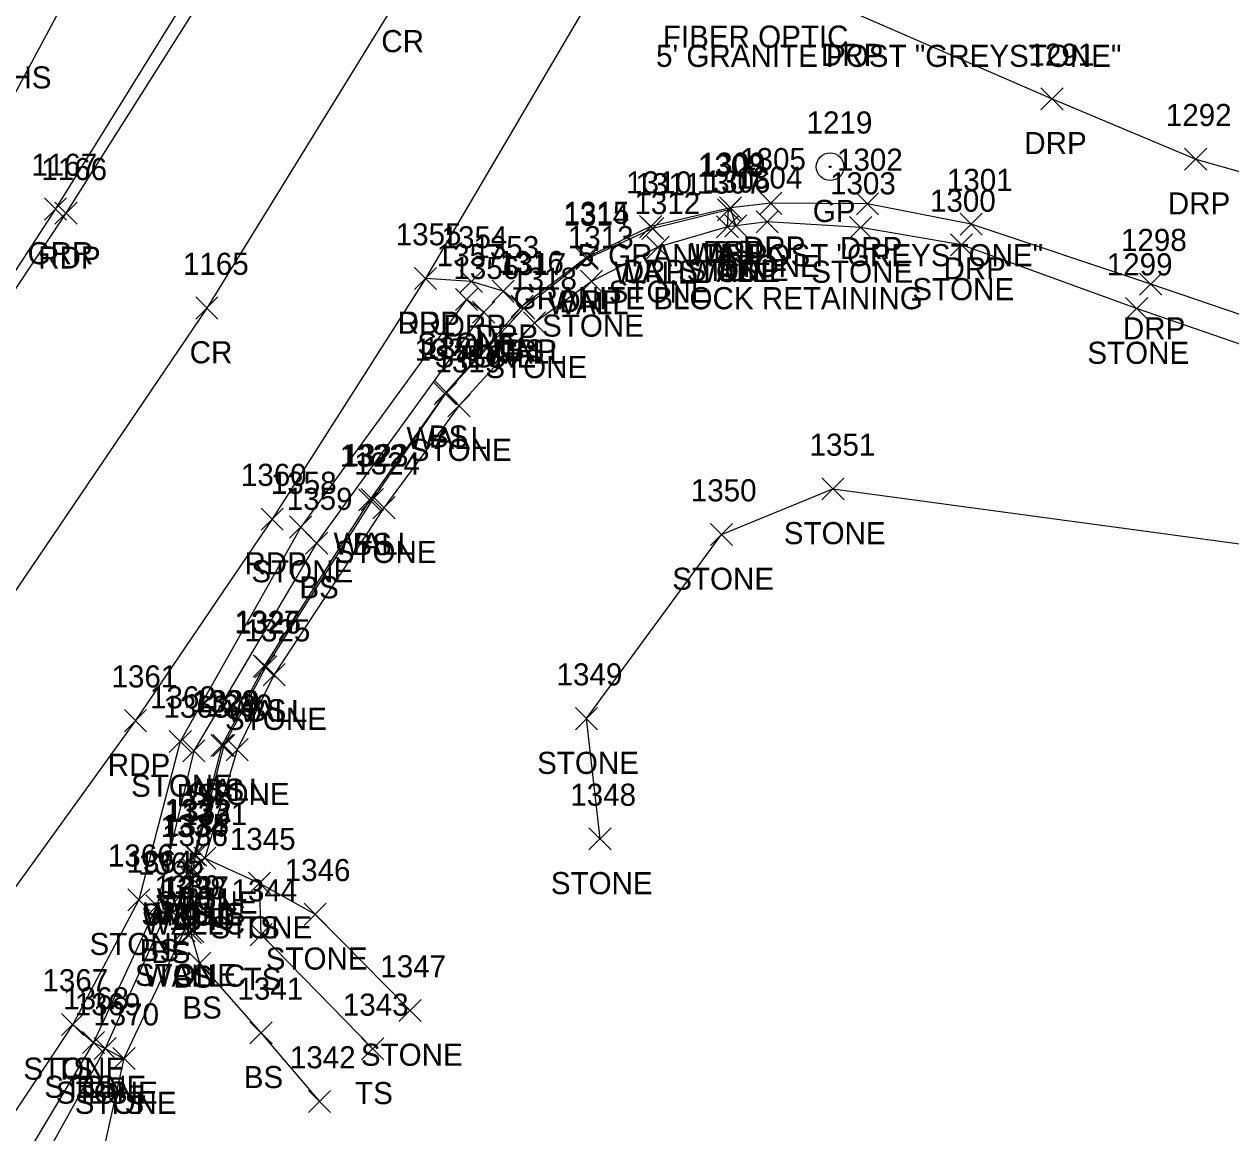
# Model space of a CAD drawing. Extents: x 1599840 to 1601211, y 518904 to 521989.
# Drawn here: x 1600815 to 1600924.1, y 521188.3 to 521288.6 of the extents above; entities that cross this region are included whole.
import ezdxf

# ---------------------------------------------------------------- set-up
doc = ezdxf.new("R2010")
doc.units = 0
for name, color, linetype in [('L_A', 7, 'Continuous'), ('L_C', 7, 'Continuous'), ('L_I', 7, 'Continuous'), ('L_TIC', 7, 'Continuous'), ('LASF', 7, 'Continuous'), ('LELB', 7, 'Continuous'), ('LW', 7, 'Continuous'), ('P_A', 7, 'Continuous'), ('P_I', 7, 'Continuous'), ('P_TIC', 7, 'Continuous'), ('PET', 7, 'Continuous'), ('PRC', 7, 'Continuous'), ('R_A', 7, 'Continuous'), ('R_C', 7, 'Continuous'), ('R_I', 7, 'Continuous'), ('R_TIC', 7, 'Continuous'), ('RDP', 7, 'Continuous'), ('RGP', 7, 'Continuous'), ('RGR', 7, 'Continuous'), ('U_A', 7, 'Continuous'), ('U_C', 7, 'Continuous')]:
    doc.layers.add(name, color=color, linetype=linetype)

msp = doc.modelspace()

# ---------------------------------------------------------------- linework, layer by layer
at = {"layer": 'L_TIC'}
for points in [[(1600877.72, 521270.83), (1600879.72, 521272.83)], [(1600879.72, 521270.83), (1600877.72, 521272.83)], [(1600877.89, 521271), (1600879.89, 521273)], [(1600879.89, 521271), (1600877.89, 521273)], [(1600881.21, 521269.74), (1600883.21, 521271.74)], [(1600883.21, 521269.74), (1600881.21, 521271.74)], [(1600870.86, 521269.14), (1600872.86, 521271.14)], [(1600872.86, 521269.14), (1600870.86, 521271.14)], [(1600877.61, 521269.29), (1600879.61, 521271.29)], [(1600879.61, 521269.29), (1600877.61, 521271.29)], [(1600877.61, 521269.29), (1600879.61, 521271.29)], [(1600879.61, 521269.29), (1600877.61, 521271.29)], [(1600878.38, 521269.38), (1600880.38, 521271.38)], [(1600880.38, 521269.38), (1600878.38, 521271.38)], [(1600878.38, 521269.38), (1600880.38, 521271.38)], [(1600880.38, 521269.38), (1600878.38, 521271.38)], [(1600889.66, 521269.22), (1600891.66, 521271.22)], [(1600891.66, 521269.22), (1600889.66, 521271.22)], [(1600871.33, 521267.43), (1600873.33, 521269.43)], [(1600873.33, 521267.43), (1600871.33, 521269.43)], [(1600898.79, 521267.65), (1600900.79, 521269.65)], [(1600900.79, 521267.65), (1600898.79, 521269.65)], [(1600864.91, 521266.38), (1600866.91, 521268.38)], [(1600866.91, 521266.38), (1600864.91, 521268.38)], [(1600865.31, 521264.35), (1600867.31, 521266.35)], [(1600867.31, 521264.35), (1600865.31, 521266.35)], [(1600854.02, 521262.72), (1600856.02, 521264.72)], [(1600856.02, 521262.72), (1600854.02, 521264.72)], [(1600859.05, 521262.1), (1600861.05, 521264.1)], [(1600861.05, 521262.1), (1600859.05, 521264.1)], [(1600855.57, 521261.56), (1600857.57, 521263.56)], [(1600857.57, 521261.56), (1600855.57, 521263.56)], [(1600855.57, 521261.56), (1600857.57, 521263.56)], [(1600857.57, 521261.56), (1600855.57, 521263.56)], [(1600859.2, 521261.92), (1600861.2, 521263.92)], [(1600861.2, 521261.92), (1600859.2, 521263.92)], [(1600914.62, 521261.89), (1600916.62, 521263.89)], [(1600916.62, 521261.89), (1600914.62, 521263.89)], [(1600860.17, 521260.6), (1600862.17, 521262.6)], [(1600862.17, 521260.6), (1600860.17, 521262.6)], [(1600852.17, 521254.32), (1600854.17, 521256.32)], [(1600854.17, 521254.32), (1600852.17, 521256.32)], [(1600852.1, 521254.18), (1600854.1, 521256.18)], [(1600854.1, 521254.18), (1600852.1, 521256.18)], [(1600853.34, 521253.11), (1600855.34, 521255.11)], [(1600855.34, 521253.11), (1600853.34, 521255.11)], [(1600887.16, 521245.58), (1600889.16, 521247.58)], [(1600889.16, 521245.58), (1600887.16, 521247.58)], [(1600845.26, 521244.59), (1600847.26, 521246.59)], [(1600847.26, 521244.59), (1600845.26, 521246.59)], [(1600845.5, 521244.63), (1600847.5, 521246.63)], [(1600847.5, 521244.63), (1600845.5, 521246.63)], [(1600846.55, 521243.88), (1600848.55, 521245.88)], [(1600848.55, 521243.88), (1600846.55, 521245.88)], [(1600839.02, 521242.13), (1600841.02, 521244.13)], [(1600841.02, 521242.13), (1600839.02, 521244.13)], [(1600877.08, 521241.45), (1600879.08, 521243.45)], [(1600879.08, 521241.45), (1600877.08, 521243.45)], [(1600840.46, 521240.68), (1600842.46, 521242.68)], [(1600842.46, 521240.68), (1600840.46, 521242.68)], [(1600835.72, 521229.56), (1600837.72, 521231.56)], [(1600837.72, 521229.56), (1600835.72, 521231.56)], [(1600835.86, 521229.49), (1600837.86, 521231.49)], [(1600837.86, 521229.49), (1600835.86, 521231.49)], [(1600836.63, 521228.78), (1600838.63, 521230.78)], [(1600838.63, 521228.78), (1600836.63, 521230.78)], [(1600864.86, 521224.8), (1600866.86, 521226.8)], [(1600866.86, 521224.8), (1600864.86, 521226.8)], [(1600828.13, 521222.73), (1600830.13, 521224.73)], [(1600830.13, 521222.73), (1600828.13, 521224.73)], [(1600829.35, 521221.88), (1600831.35, 521223.88)], [(1600831.35, 521221.88), (1600829.35, 521223.88)], [(1600831.9, 521222.37), (1600833.9, 521224.37)], [(1600833.9, 521222.37), (1600831.9, 521224.37)], [(1600832.07, 521222.37), (1600834.07, 521224.37)], [(1600834.07, 521222.37), (1600832.07, 521224.37)], [(1600833.27, 521221.99), (1600835.27, 521223.99)], [(1600835.27, 521221.99), (1600833.27, 521223.99)], [(1600866.09, 521213.92), (1600868.09, 521215.92)], [(1600868.09, 521213.92), (1600866.09, 521215.92)], [(1600829.39, 521212.52), (1600831.39, 521214.52)], [(1600831.39, 521212.52), (1600829.39, 521214.52)], [(1600829.52, 521212.46), (1600831.52, 521214.46)], [(1600831.52, 521212.46), (1600829.52, 521214.46)], [(1600830.35, 521212.17), (1600832.35, 521214.17)], [(1600832.35, 521212.17), (1600830.35, 521214.17)], [(1600829.05, 521211.08), (1600831.05, 521213.08)], [(1600831.05, 521211.08), (1600829.05, 521213.08)], [(1600829.05, 521211.08), (1600831.05, 521213.08)], [(1600831.05, 521211.08), (1600829.05, 521213.08)], [(1600829.28, 521211.17), (1600831.28, 521213.17)], [(1600831.28, 521211.17), (1600829.28, 521213.17)], [(1600829.28, 521211.17), (1600831.28, 521213.17)], [(1600831.28, 521211.17), (1600829.28, 521213.17)], [(1600829.24, 521210.27), (1600831.24, 521212.27)], [(1600831.24, 521210.27), (1600829.24, 521212.27)], [(1600835.3, 521209.92), (1600837.3, 521211.92)], [(1600837.3, 521209.92), (1600835.3, 521211.92)], [(1600835.3, 521209.92), (1600837.3, 521211.92)], [(1600837.3, 521209.92), (1600835.3, 521211.92)], [(1600824.38, 521208.42), (1600826.38, 521210.42)], [(1600826.38, 521208.42), (1600824.38, 521210.42)], [(1600826.01, 521207.86), (1600828.01, 521209.86)], [(1600828.01, 521207.86), (1600826.01, 521209.86)], [(1600827.05, 521207.69), (1600829.05, 521209.69)], [(1600829.05, 521207.69), (1600827.05, 521209.69)], [(1600840.32, 521207.1), (1600842.32, 521209.1)], [(1600842.32, 521207.1), (1600840.32, 521209.1)], [(1600828.49, 521205.62), (1600830.49, 521207.62)], [(1600830.49, 521205.62), (1600828.49, 521207.62)], [(1600829.05, 521205.46), (1600831.05, 521207.46)], [(1600831.05, 521205.46), (1600829.05, 521207.46)], [(1600829.27, 521205.55), (1600831.27, 521207.55)], [(1600831.27, 521205.55), (1600829.27, 521207.55)], [(1600835.45, 521205.26), (1600837.45, 521207.26)], [(1600837.45, 521205.26), (1600835.45, 521207.26)], [(1600829.88, 521202.67), (1600831.88, 521204.67)], [(1600831.88, 521202.67), (1600829.88, 521204.67)], [(1600848.91, 521198.4), (1600850.91, 521200.4)], [(1600850.91, 521198.4), (1600848.91, 521200.4)], [(1600818.4, 521197.14), (1600820.4, 521199.14)], [(1600820.4, 521197.14), (1600818.4, 521199.14)], [(1600818.4, 521197.14), (1600820.4, 521199.14)], [(1600820.4, 521197.14), (1600818.4, 521199.14)], [(1600820.28, 521195.5), (1600822.28, 521197.5)], [(1600822.28, 521195.5), (1600820.28, 521197.5)], [(1600820.28, 521195.5), (1600822.28, 521197.5)], [(1600822.28, 521195.5), (1600820.28, 521197.5)], [(1600835.43, 521196.38), (1600837.43, 521198.38)], [(1600837.43, 521196.38), (1600835.43, 521198.38)], [(1600821.34, 521194.97), (1600823.34, 521196.97)], [(1600823.34, 521194.97), (1600821.34, 521196.97)], [(1600821.34, 521194.97), (1600823.34, 521196.97)], [(1600823.34, 521194.97), (1600821.34, 521196.97)], [(1600845.53, 521194.93), (1600847.53, 521196.93)], [(1600847.53, 521194.93), (1600845.53, 521196.93)], [(1600823.04, 521194.05), (1600825.04, 521196.05)], [(1600825.04, 521194.05), (1600823.04, 521196.05)], [(1600823.04, 521194.05), (1600825.04, 521196.05)], [(1600825.04, 521194.05), (1600823.04, 521196.05)], [(1600823.04, 521194.05), (1600825.04, 521196.05)], [(1600825.04, 521194.05), (1600823.04, 521196.05)], [(1600840.73, 521190.17), (1600842.73, 521192.17)], [(1600842.73, 521190.17), (1600840.73, 521192.17)]]:
    msp.add_lwpolyline(points, dxfattribs=at)
at = {"layer": 'LASF'}
for points in [[(1600932.23, 521257.16), (1600915.62, 521262.89), (1600899.79, 521268.65), (1600890.66, 521270.22), (1600882.21, 521270.74), (1600879.38, 521270.38), (1600878.61, 521270.29), (1600872.33, 521268.43), (1600866.31, 521265.35), (1600861.17, 521261.6), (1600854.34, 521254.11), (1600847.55, 521244.88), (1600837.63, 521229.78), (1600834.27, 521222.99), (1600831.35, 521213.17), (1600836.3, 521210.92), (1600841.32, 521208.1), (1600849.91, 521199.4)], [(1600856.57, 521262.56), (1600855.02, 521263.72), (1600840.02, 521243.13), (1600829.13, 521223.73), (1600825.38, 521209.42), (1600819.4, 521198.14), (1600821.28, 521196.5), (1600822.34, 521195.97), (1600824.04, 521195.05)], [(1600867.09, 521214.92), (1600865.86, 521225.8), (1600878.08, 521242.45), (1600888.16, 521246.58), (1600929.62, 521240.98)], [(1600830.05, 521212.08), (1600829.49, 521206.62), (1600824.04, 521195.05)]]:
    msp.add_lwpolyline(points, dxfattribs=at)
at = {"layer": 'LELB'}
for points in [[(1600833.08, 521322.84), (1600827.14, 521306.56), (1600810.92, 521276.32), (1600800.69, 521262.52), (1600794.58, 521254.04), (1600785.73, 521239.52), (1600767.25, 521213.82), (1600747.49, 521193.49), (1600721.35, 521163.12)], [(1600879.38, 521270.38), (1600878.89, 521272)], [(1600860.05, 521263.1), (1600853.17, 521255.32), (1600846.26, 521245.59), (1600836.72, 521230.56), (1600832.9, 521223.37), (1600830.39, 521213.52), (1600830.05, 521212.08), (1600830.05, 521206.46), (1600830.88, 521203.67), (1600836.43, 521197.38), (1600841.73, 521191.17)], [(1600856.57, 521262.56), (1600841.46, 521241.68), (1600830.35, 521222.88), (1600827.01, 521208.86), (1600821.28, 521196.5), (1600810.47, 521178.41), (1600803.33, 521166.07), (1600804.2, 521165.56)], [(1600846.53, 521195.93), (1600836.45, 521206.26), (1600836.3, 521210.92)], [(1600828.05, 521208.69), (1600822.34, 521195.97), (1600812.05, 521177.48), (1600804.2, 521165.56)], [(1600819.4, 521198.14), (1600807.49, 521180.18), (1600800.87, 521166.44)], [(1600824.04, 521195.05), (1600819.31, 521173.94), (1600807, 521160.6), (1600803.28, 521163.71), (1600800.87, 521166.44)]]:
    msp.add_lwpolyline(points, dxfattribs=at)
at = {"layer": 'LW'}
for points in [[(1600878.61, 521270.29), (1600878.72, 521271.83), (1600871.86, 521270.14), (1600865.91, 521267.38), (1600860.2, 521262.92), (1600853.1, 521255.18), (1600846.5, 521245.63), (1600836.86, 521230.49), (1600833.07, 521223.37), (1600830.52, 521213.46), (1600830.28, 521212.17)], [(1600830.28, 521212.17), (1600830.24, 521211.27), (1600830.27, 521206.55)]]:
    msp.add_lwpolyline(points, dxfattribs=at)
at = {"layer": 'P_TIC'}
for points in [[(1600817.79, 521270.51), (1600819.79, 521272.51)], [(1600819.79, 521270.51), (1600817.79, 521272.51)], [(1600850.3, 521264.61), (1600852.3, 521266.61)], [(1600852.3, 521264.61), (1600850.3, 521266.61)], [(1600830.54, 521261.94), (1600832.54, 521263.94)], [(1600832.54, 521261.94), (1600830.54, 521263.94)], [(1600836.44, 521242.85), (1600838.44, 521244.85)], [(1600838.44, 521242.85), (1600836.44, 521244.85)], [(1600824.08, 521224.62), (1600826.08, 521226.62)], [(1600826.08, 521224.62), (1600824.08, 521226.62)]]:
    msp.add_lwpolyline(points, dxfattribs=at)
at = {"layer": 'PET'}
for points in [[(1600925.83, 521507.52), (1600915.18, 521473.31), (1600903.26, 521440.28), (1600887.48, 521401.44), (1600873.35, 521370.15), (1600860.38, 521343.64), (1600847.93, 521319.69), (1600844.65, 521313.14), (1600836.72, 521299.9), (1600818.79, 521271.51), (1600793.69, 521233.92), (1600774.49, 521208.06), (1600757.09, 521185.54), (1600730.91, 521154.49)], [(1600955.79, 521499.34), (1600943.51, 521460.9), (1600932.49, 521430.95), (1600915.63, 521388.21), (1600902.46, 521359.92), (1600888.21, 521330.27), (1600876.23, 521308.06), (1600874.78, 521305.59), (1600851.3, 521265.61), (1600837.44, 521243.85), (1600825.08, 521225.62), (1600799.95, 521190.82), (1600794.12, 521183.15), (1600773.8, 521157.79), (1600751.79, 521131.81)]]:
    msp.add_lwpolyline(points, dxfattribs=at)
at = {"layer": 'PRC'}
msp.add_lwpolyline([(1600941.11, 521503.3), (1600929.22, 521466.1), (1600917.95, 521435.49), (1600901.05, 521394.76), (1600888.43, 521365.83), (1600873.97, 521336.55), (1600862.78, 521315.41), (1600848.88, 521291.08), (1600831.54, 521262.94), (1600805.42, 521224.44), (1600786.95, 521198.81), (1600768.67, 521175.32), (1600742.32, 521144.02)], dxfattribs=at)
at = {"layer": 'R_TIC'}
for points in [[(1600906.97, 521280.86), (1600908.97, 521282.86)], [(1600908.97, 521280.86), (1600906.97, 521282.86)], [(1600919.96, 521275.4), (1600921.96, 521277.4)], [(1600921.96, 521275.4), (1600919.96, 521277.4)], [(1600816.84, 521270.9), (1600818.84, 521272.9)], [(1600818.84, 521270.9), (1600816.84, 521272.9)], [(1600877.89, 521271), (1600879.89, 521273)], [(1600879.89, 521271), (1600877.89, 521273)], [(1600881.54, 521271.41), (1600883.54, 521273.41)], [(1600883.54, 521271.41), (1600881.54, 521273.41)], [(1600890.29, 521271.36), (1600892.29, 521273.36)], [(1600892.29, 521271.36), (1600890.29, 521273.36)], [(1600870.67, 521269.3), (1600872.67, 521271.3)], [(1600872.67, 521269.3), (1600870.67, 521271.3)], [(1600899.66, 521269.53), (1600901.66, 521271.53)], [(1600901.66, 521269.53), (1600899.66, 521271.53)], [(1600864.92, 521266.55), (1600866.92, 521268.55)], [(1600866.92, 521266.55), (1600864.92, 521268.55)], [(1600850.3, 521264.61), (1600852.3, 521266.61)], [(1600852.3, 521264.61), (1600850.3, 521266.61)], [(1600854.45, 521264.34), (1600856.45, 521266.34)], [(1600856.45, 521264.34), (1600854.45, 521266.34)], [(1600915.89, 521264.1), (1600917.89, 521266.1)], [(1600917.89, 521264.1), (1600915.89, 521266.1)], [(1600857.33, 521263.45), (1600859.33, 521265.45)], [(1600859.33, 521263.45), (1600857.33, 521265.45)], [(1600859.05, 521262.1), (1600861.05, 521264.1)], [(1600861.05, 521262.1), (1600859.05, 521264.1)]]:
    msp.add_lwpolyline(points, dxfattribs=at)
at = {"layer": 'RDP'}
for points in [[(1600874.78, 521305.59), (1600877.36, 521296.17), (1600889.58, 521289.84), (1600907.97, 521281.86), (1600920.96, 521276.4), (1600937.85, 521271.62)], [(1600933.18, 521259.54), (1600916.89, 521265.1), (1600900.66, 521270.53), (1600891.29, 521272.36), (1600882.54, 521272.41), (1600878.89, 521272), (1600871.67, 521270.3), (1600865.92, 521267.55), (1600860.05, 521263.1), (1600858.33, 521264.45), (1600855.45, 521265.34), (1600851.3, 521265.61)]]:
    msp.add_lwpolyline(points, dxfattribs=at)
at = {"layer": 'RGP'}
msp.add_line((1600887.9, 521275.72), (1600887.9, 521275.72), dxfattribs=at)
for radius in [1.25, 0.0833]:
    msp.add_circle((1600887.9, 521275.72), radius, dxfattribs=at)
at = {"layer": 'RGR'}
msp.add_lwpolyline([(1600826.09, 521344.21), (1600833.69, 521339.74), (1600838.12, 521335.63), (1600842.43, 521329.4), (1600844.67, 521324.01), (1600845, 521318.73), (1600843.51, 521313.73), (1600835.63, 521300.64), (1600817.84, 521271.9), (1600810.24, 521260.24), (1600806.53, 521256.68), (1600802.26, 521254.42), (1600799.01, 521253.84)], dxfattribs=at)

# ---------------------------------------------------------------- texts
at = {"layer": 'L_A'}
for s, p in [('WALL', (1600875.21, 521266.83)), ('BS', (1600877.33, 521267)), ('STONE', (1600874.16, 521265.29)), ('STONE', (1600874.92, 521265.38)), ('WALL', (1600875.1, 521265.29)), ('STONE', (1600877.75, 521265.74)), ('BS', (1600877.82, 521265.38)), ('STONE', (1600886.2, 521265.22)), ('WALL', (1600868.34, 521265.14)), ('STONE', (1600867.87, 521263.43)), ('STONE', (1600895.33, 521263.65)), ('WALL', (1600862.4, 521262.38)), ('STONE', (1600861.85, 521260.35)), ('STONE', (1600850.56, 521258.72)), ('STONE', (1600852.12, 521257.56)), ('BS', (1600855.01, 521257.56)), ('WALL', (1600856.69, 521257.92)), ('BS', (1600858.49, 521258.1)), ('STONE', (1600911.16, 521257.89)), ('STONE', (1600856.72, 521256.6)), ('WALL', (1600849.59, 521250.18)), ('BS', (1600851.61, 521250.32)), ('STONE', (1600849.89, 521249.11)), ('STONE', (1600883.71, 521241.58)), ('WALL', (1600842.99, 521240.63)), ('BS', (1600844.7, 521240.59)), ('STONE', (1600843.09, 521239.88)), ('STONE', (1600835.56, 521238.13)), ('STONE', (1600873.62, 521237.45)), ('BS', (1600839.9, 521236.68)), ('WALL', (1600833.35, 521225.49)), ('BS', (1600835.16, 521225.56)), ('STONE', (1600833.17, 521224.78)), ('STONE', (1600861.4, 521220.8)), ('STONE', (1600824.68, 521218.73)), ('WALL', (1600829.55, 521218.37)), ('BS', (1600831.34, 521218.37)), ('BS', (1600828.79, 521217.88)), ('STONE', (1600829.81, 521217.99)), ('STONE', (1600862.64, 521209.92)), ('WALL', (1600827.01, 521208.46)), ('BS', (1600828.83, 521208.52)), ('STONE', (1600826.9, 521208.17)), ('STONE', (1600825.59, 521207.08)), ('WALLC', (1600825.78, 521206.27)), ('WALLC', (1600825.82, 521207.17)), ('WALL', (1600826.77, 521207.17)), ('BS', (1600828.49, 521207.08)), ('STONE', (1600831.85, 521205.92)), ('TS', (1600834.71, 521205.92)), ('STONE', (1600820.92, 521204.42)), ('BS', (1600825.45, 521203.86)), ('BS', (1600826.49, 521203.69)), ('STONE', (1600836.86, 521203.1)), ('STONE', (1600825.03, 521201.62)), ('WALLC', (1600825.81, 521201.55)), ('BS', (1600828.49, 521201.46)), ('TS', (1600834.86, 521201.26)), ('BS', (1600829.32, 521198.67)), ('STONE', (1600845.46, 521194.4)), ('STONE', (1600814.94, 521193.14)), ('TS', (1600817.81, 521193.14)), ('BS', (1600834.87, 521192.38)), ('STONE', (1600816.83, 521191.5)), ('STONE', (1600817.88, 521190.97)), ('BS', (1600819.72, 521191.5)), ('BS', (1600820.78, 521190.97)), ('STONE', (1600819.58, 521190.05)), ('STONE', (1600819.58, 521190.05)), ('TS', (1600822.45, 521190.05)), ('TS', (1600844.94, 521190.93))]:
    msp.add_text(s, height=2, dxfattribs=at).set_placement(p)
at = {"layer": 'L_C'}
msp.add_text('GRANITE BLOCK RETAINING', height=2, dxfattribs=at).set_placement((1600859.28, 521262.83))
at = {"layer": 'L_I'}
for s, p in [('1309', (1600876.11, 521275)), ('1308', (1600875.95, 521274.83)), ('1311', (1600870.3, 521273.14)), ('1307', (1600875.84, 521273.29)), ('1307', (1600875.84, 521273.29)), ('1306', (1600876.55, 521273.38)), ('1306', (1600876.55, 521273.38)), ('1304', (1600879.44, 521273.74)), ('1303', (1600887.89, 521273.22)), ('1312', (1600870.2, 521271.43)), ('1300', (1600896.93, 521271.65)), ('1314', (1600863.78, 521270.38)), ('1313', (1600864.18, 521268.35)), ('1357', (1600852.32, 521266.72)), ('1356', (1600853.83, 521265.56)), ('1356', (1600853.83, 521265.56)), ('1316', (1600857.87, 521266.1)), ('1317', (1600858.07, 521265.92)), ('1299', (1600912.92, 521265.89)), ('1318', (1600859.05, 521264.6)), ('1320', (1600850.32, 521258.18)), ('1321', (1600851.04, 521258.32)), ('1319', (1600852.21, 521257.11)), ('1351', (1600886.04, 521249.58)), ('1322', (1600843.56, 521248.59)), ('1323', (1600843.81, 521248.63)), ('1324', (1600844.86, 521247.88)), ('1358', (1600837.32, 521246.13)), ('1359', (1600838.76, 521244.68)), ('1350', (1600875.3, 521245.45)), ('1327', (1600834.03, 521233.56)), ('1326', (1600834.11, 521233.49)), ('1325', (1600834.94, 521232.78)), ('1349', (1600863.16, 521228.8)), ('1362', (1600826.39, 521226.73)), ('1363', (1600827.61, 521225.88)), ('1328', (1600830.21, 521226.37)), ('1329', (1600830.36, 521226.37)), ('1330', (1600831.49, 521225.99)), ('1348', (1600864.4, 521217.92)), ('1333', (1600827.69, 521216.52)), ('1332', (1600827.83, 521216.46)), ('1331', (1600829.23, 521216.17)), ('1334', (1600827.35, 521215.08)), ('1334', (1600827.35, 521215.08)), ('1335', (1600827.59, 521215.17)), ('1335', (1600827.59, 521215.17)), ('1336', (1600827.49, 521214.27)), ('1345', (1600833.61, 521213.92)), ('1345', (1600833.61, 521213.92)), ('1366', (1600822.58, 521212.42)), ('1364', (1600824.27, 521211.86)), ('1365', (1600825.31, 521211.69)), ('1346', (1600838.57, 521211.1)), ('1339', (1600826.79, 521209.62)), ('1337', (1600827.58, 521209.55)), ('1338', (1600827.35, 521209.46)), ('1344', (1600833.76, 521209.26)), ('1340', (1600828.1, 521206.67)), ('1347', (1600847.22, 521202.4)), ('1367', (1600816.66, 521201.14)), ('1367', (1600816.66, 521201.14)), ('1341', (1600834.3, 521200.38)), ('1368', (1600818.54, 521199.5)), ('1368', (1600818.54, 521199.5)), ('1369', (1600819.59, 521198.97)), ('1369', (1600819.59, 521198.97)), ('1343', (1600843.83, 521198.93)), ('1370', (1600821.26, 521198.05)), ('1370', (1600821.26, 521198.05)), ('1370', (1600821.26, 521198.05)), ('1342', (1600839.04, 521194.17))]:
    msp.add_text(s, height=2, dxfattribs=at).set_placement(p)
at = {"layer": 'P_A'}
for s, p in [('CR', (1600847.31, 521286.08)), ('RDP', (1600816.28, 521266.51)), ('RDP', (1600848.79, 521260.61)), ('CR', (1600829.98, 521257.94)), ('RDP', (1600834.93, 521238.85)), ('RDP', (1600822.57, 521220.62))]:
    msp.add_text(s, height=2, dxfattribs=at).set_placement(p)
at = {"layer": 'P_I'}
for s, p in [('1166', (1600816.56, 521274.51)), ('1355', (1600848.61, 521268.61)), ('1165', (1600829.37, 521265.94)), ('1360', (1600834.61, 521246.85)), ('1361', (1600822.91, 521228.62))]:
    msp.add_text(s, height=2, dxfattribs=at).set_placement(p)
at = {"layer": 'R_A'}
for s, p in [('DRP', (1600887.07, 521284.84)), ('DRP', (1600905.46, 521276.86)), ('GP', (1600886.33, 521270.72)), ('DRP', (1600918.44, 521271.4)), ('DRP', (1600880.02, 521267.41)), ('GRR', (1600815.32, 521266.9)), ('DRP', (1600876.38, 521267)), ('DRP', (1600888.78, 521267.36)), ('DRP', (1600869.15, 521265.3)), ('DRP', (1600898.15, 521265.53)), ('DRP', (1600863.41, 521262.55)), ('DRP', (1600848.79, 521260.61)), ('DRP', (1600852.94, 521260.34)), ('DRP', (1600914.38, 521260.1)), ('DRP', (1600855.82, 521259.45)), ('DRP', (1600857.54, 521258.1))]:
    msp.add_text(s, height=2, dxfattribs=at).set_placement(p)
at = {"layer": 'R_C'}
for p in [(1600872.16, 521284.75), (1600865.08, 521266.72)]:
    msp.add_text('5\' GRANITE POST "GREYSTONE"', height=2, dxfattribs=at).set_placement(p)
at = {"layer": 'R_I'}
for s, p in [('1291', (1600905.84, 521284.86)), ('1292', (1600918.26, 521279.4)), ('1219', (1600885.77, 521278.72)), ('1309', (1600876.11, 521275)), ('1305', (1600879.76, 521275.41)), ('1302', (1600888.52, 521275.36)), ('1167', (1600815.66, 521274.9)), ('1310', (1600869.45, 521273.3)), ('1301', (1600898.46, 521273.53)), ('1315', (1600863.8, 521270.55)), ('1355', (1600848.61, 521268.61)), ('1354', (1600852.76, 521268.34)), ('1353', (1600855.64, 521267.45)), ('1298', (1600914.2, 521268.1)), ('1316', (1600857.87, 521266.1))]:
    msp.add_text(s, height=2, dxfattribs=at).set_placement(p)
at = {"layer": 'U_A'}
msp.add_text('MHS', height=2, dxfattribs=at).set_placement((1600811.54, 521282.8))
at = {"layer": 'U_C'}
msp.add_text('FIBER OPTIC', height=2, dxfattribs=at).set_placement((1600872.77, 521286.49))

doc.saveas('drawing.dxf')
